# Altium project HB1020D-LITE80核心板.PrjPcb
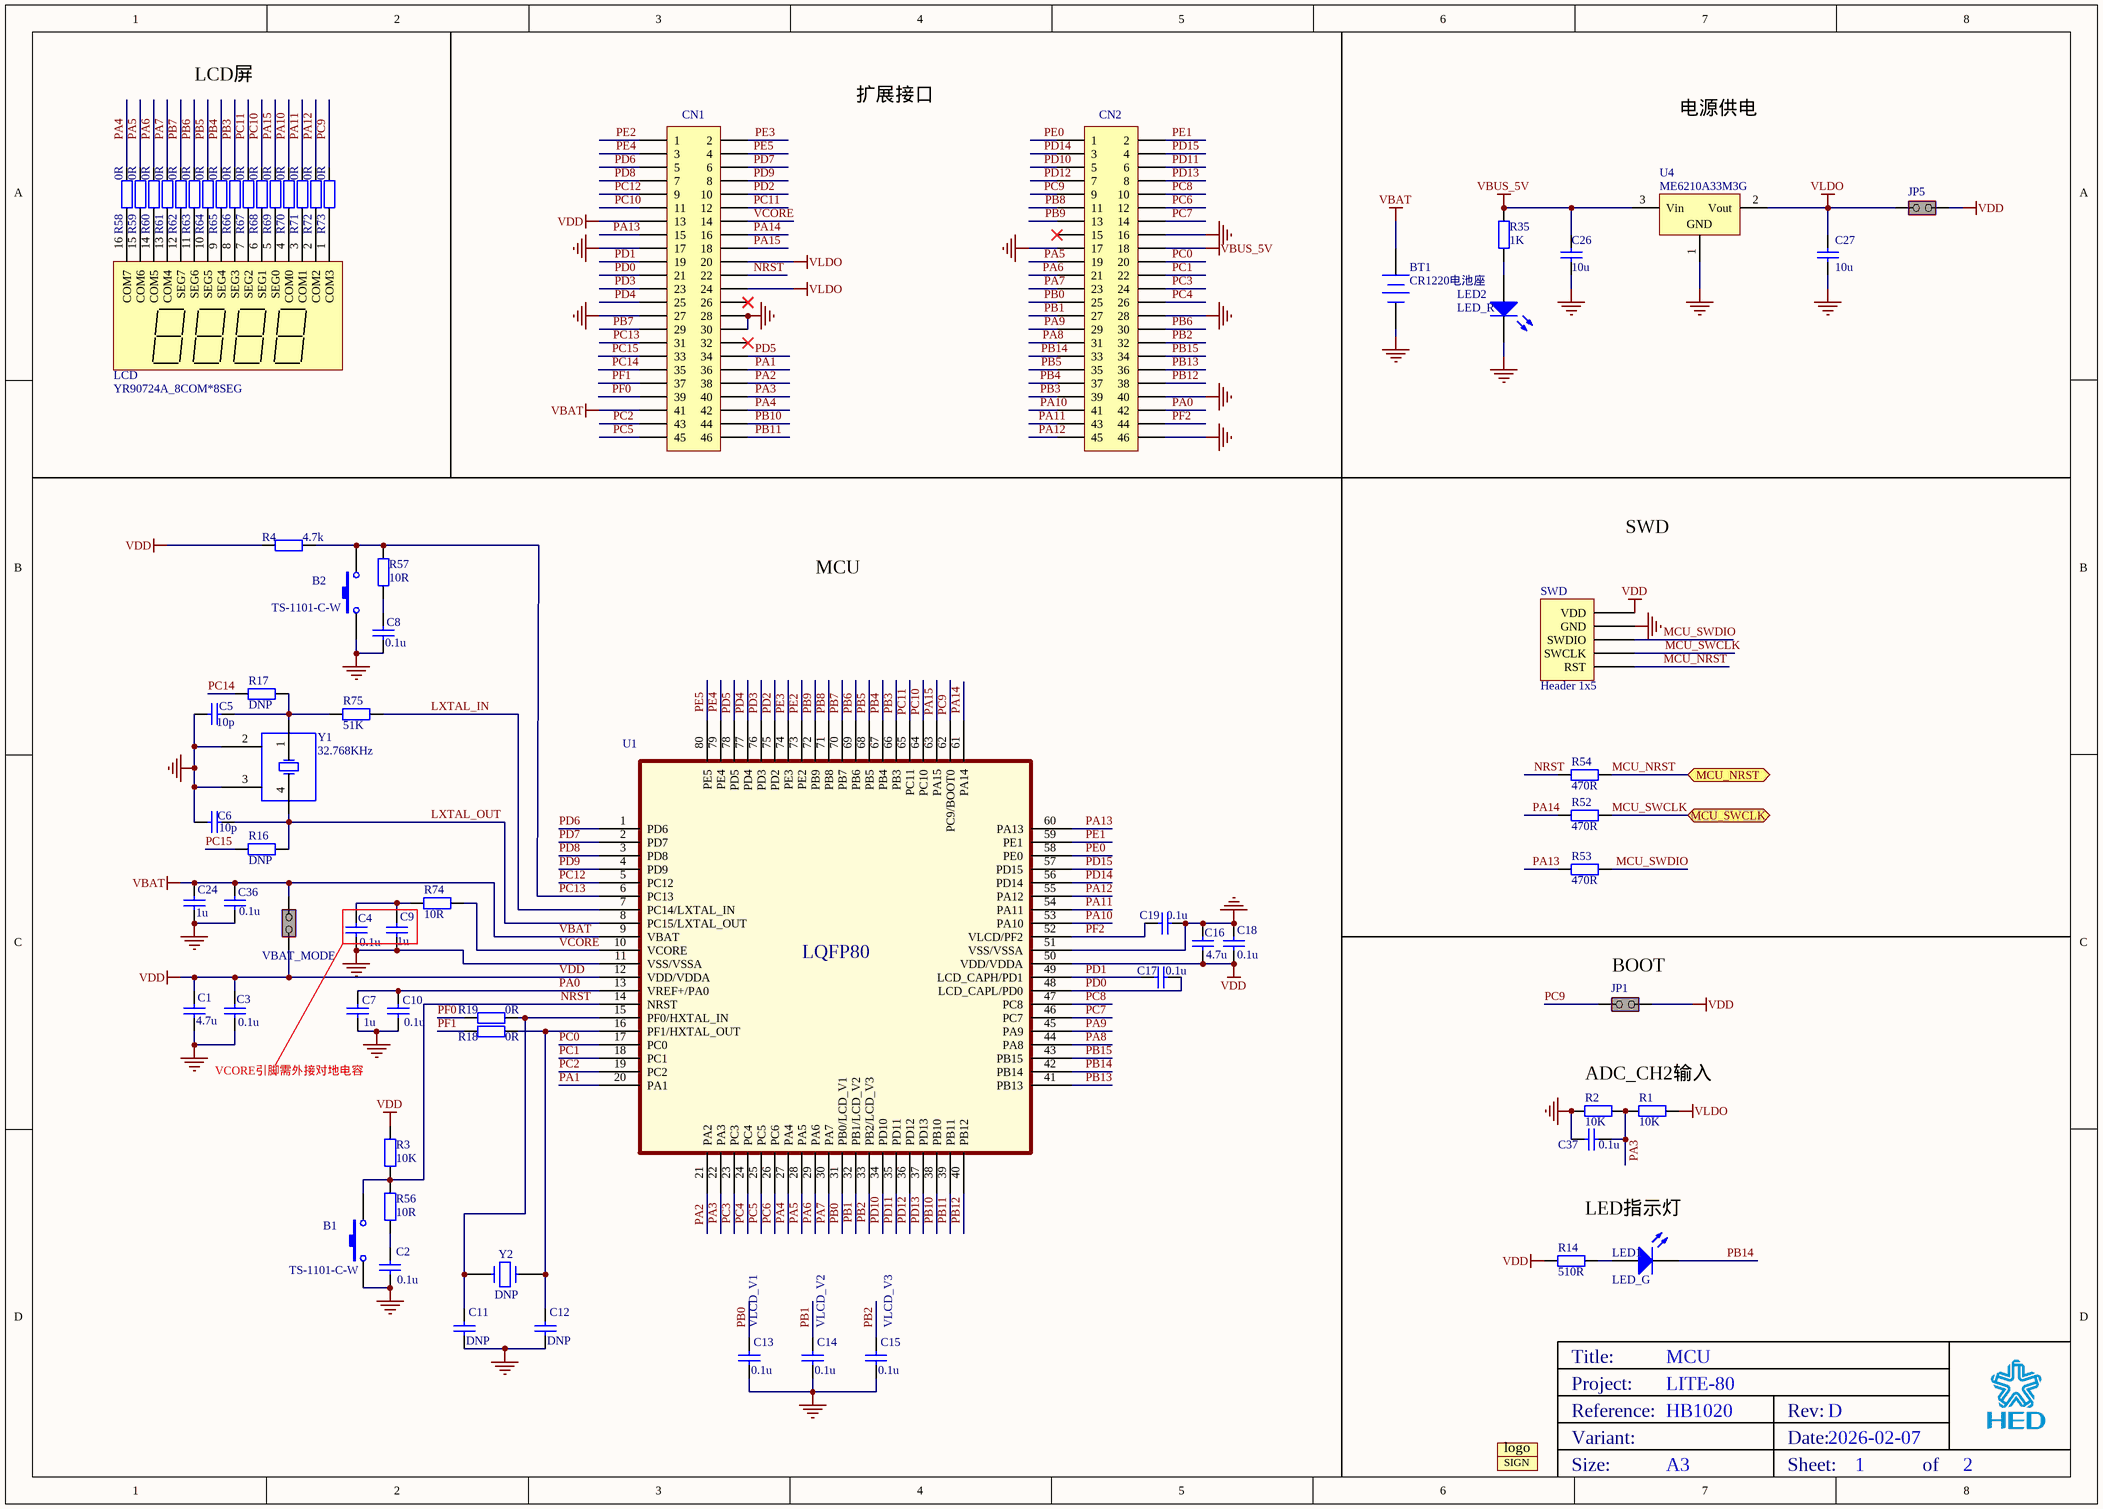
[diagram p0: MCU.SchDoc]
Board_Assembly_Revision: 01; Board_Name: LITE-80; Board_PCB_Revision: D; Board_Reference: HB1020
2 sheets, 115 parts. Net scope: global (net labels, ports and power ports of the same name join across sheets).
Board file: HB1020D.PcbDoc
Sheets:
  MCU.SchDoc
  LINK.SchDoc

## Sheet MCU.SchDoc: MCU
size A3; Date: 2026-02-07; SheetNumber: 1; SheetTotal: 2

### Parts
B1  TS-1101-C-W  [按键_TS-1101-C-W]
B2  TS-1101-C-W  [按键_TS-1101-C-W]
BT1  CR1220电池座  [CR1220]
C1  4.7u  [0603]
C2  0.1u  [0603]
C3  0.1u  [0603]
C4  0.1u  [0603]
C5  10p  [0603]
C6  10p  [0603]
C7  1u  [0603]
C8  0.1u  [0603]
C9  1u  [0603]
C10  0.1u  [0603]
C11  DNP  [0603]
C12  DNP  [0603]
C13  0.1u  [0603]
C14  0.1u  [0603]
C15  0.1u  [0603]
C16  4.7u  [0603]
C17  0.1u  [0603]
C18  0.1u  [0603]
C19  0.1u  [0603]
C24  1u  [0603]
C26  10u  [0603]
C27  10u  [0603]
C36  0.1u  [0603]
C37  0.1u  [0603]
CN1  Header 23x2  [HEADER_1X23_2.54]  (value not drawn)
CN2  Header 23x2  [HEADER_1X23_2.54]  (value not drawn)
JP1  Header 1x2  [HEADER_1X2_2.54]  (value not drawn)
JP5  Header 1x2  [HEADER_1X2_2.54]  (value not drawn)
LCD  YR90724A_8COM*8SEG  [LCD_YR_8COM*8SEG]
LED1  LED_G  [0603 - p]
LED2  LED_R  [0603-P]
logo1  logo  [LOGO]  (value not drawn)
logo2  SIGN  [SIGN]  (value not drawn)
R1  10K  [0603]
R2  10K  [0603]
R3  10K  [0603]
R4  4.7k  [0603]
R14  510R  [0603]
R16  DNP  [0603]
R17  DNP  [0603]
R18  0R  [0603]
R19  0R  [0603]
R35  1K  [0603]
R52  470R  [0603]
R53  470R  [0603]
R54  470R  [0603]
R56  10R  [0603]
R57  10R  [0603]
R58  0R  [0603]
R59  0R  [0603]
R60  0R  [0603]
R61  0R  [0603]
R62  0R  [0603]
R63  0R  [0603]
R64  0R  [0603]
R65  0R  [0603]
R66  0R  [0603]
R67  0R  [0603]
R68  0R  [0603]
R69  0R  [0603]
R70  0R  [0603]
R71  0R  [0603]
R72  0R  [0603]
R73  0R  [0603]
R74  10R  [0603]
R75  51K  [0603]
SWD  Header 1x5  [HDR1X5_2.54]
U1  (no value)  [LQFP_80N_12X12]
U4  ME6210A33M3G  [SOT-23-3]
VBAT_MODE  Header 1x2  [HEADER_1X2_2.54]  (value not drawn)
Y1  32.768KHz  [XTAL-MC146]
Y2  DNP  [XTAL_HC49/SMD]

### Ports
MCU_NRST, MCU_SWCLK

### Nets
GND: B1.1 B2.1 BT1.2(-) C1.1 C2.2 C3.1 C4.2 C5.1 C6.1 C7.1 C8.1 C9.2 C10.1 C11.2 C12.2 C13.2 C14.2 C15.2 C16.2 C18.2 C19.1 C24.1 C26.1 C27.1 C36.1 C37.2 CN1.17 CN1.27 CN1.28 CN1.30 CN2.16 CN2.17 CN2.28 CN2.40 CN2.46 LED2.2(K) R2.1 SWD.2(GND) U1.11(VSS/VSSA) U1.51(VSS/VSSA) U4.1(GND) Y1.2(OSC2) Y1.3(OSC4)
VBAT: BT1.1(+) C24.2 C36.2 CN1.41 U1.9(VBAT) VBAT_MODE.2(NO)
VBUS_5V: C26.2 CN2.18 R35.2 U4.3(Vin)
VDD: C1.2 C3.2 C16.1 C18.1 CN1.13 JP1.2(NO) JP5.1(COMMON) R3.1 R4.2 R14.2 SWD.1(VDD) U1.12(VDD/VDDA) U1.50(VDD/VDDA) VBAT_MODE.1(COMMON)
VLDO: C27.2 CN1.20 CN1.24 JP5.2(NO) R1.2 U4.2(Vout)
LXTAL_IN: R75.2 U1.7(PC14/LXTAL_IN)
LXTAL_OUT: C6.2 R16.2 U1.8(PC15/LXTAL_OUT) Y1.4(OSC3)
MCU_NRST: R54.1 SWD.5(RST) ; port MCU_NRST  [project net LINK_RESET]
MCU_SWCLK: R52.1 SWD.4(SWCLK) ; port MCU_SWCLK
MCU_SWDIO: R53.1 SWD.3(SWDIO)
NRST: B1.2 CN1.22 R3.2 R54.2 R56.1 U1.14(NRST)
PA0: C7.2 C10.2 CN2.42 U1.13(VREF+/PA0)
PA1: CN1.36 U1.20(PA1)
PA2: CN1.38 U1.21(PA2)
PA3: C37.1 CN1.40 R1.1 R2.2 U1.22(PA3)
PA4: CN1.42 R58.1 U1.27(PA4)
PA5: CN2.19 R59.1 U1.28(PA5)
PA6: CN2.21 R60.1 U1.29(PA6)
PA7: CN2.23 R61.1 U1.30(PA7)
PA8: CN2.31 U1.44(PA8)
PA9: CN2.29 U1.45(PA9)
PA10: CN2.41 R70.1 U1.53(PA10)
PA11: CN2.43 R71.1 U1.54(PA11)
PA12: CN2.45 R72.1 U1.55(PA12)
PA13: CN1.15 R53.2 U1.60(PA13)
PA14: CN1.16 R52.2 U1.61(PA14)
PA15: CN1.18 R69.1 U1.63(PA15)
PB0: C13.1 CN2.25 U1.31(PB0/LCD_V1)
PB1: C14.1 CN2.27 U1.32(PB1/LCD_V2)
PB2: C15.1 CN2.32 U1.33(PB2/LCD_V3)
PB3: CN2.39 R66.1 U1.66(PB3)
PB4: CN2.37 R65.1 U1.67(PB4)
PB5: CN2.35 R64.1 U1.68(PB5)
PB6: CN2.30 R63.1 U1.69(PB6)
PB7: CN1.29 R62.1 U1.70(PB7)
PB8: CN2.11 U1.71(PB8)
PB9: CN2.13 U1.72(PB9)
PB10: CN1.44 U1.38(PB10)
PB11: CN1.46 U1.39(PB11)
PB12: CN2.38 U1.40(PB12)
PB13: CN2.36 U1.41(PB13)
PB14: CN2.33 LED1.2(K) U1.42(PB14)
PB15: CN2.34 U1.43(PB15)
PC0: CN2.20 U1.17(PC0)
PC1: CN2.22 U1.18(PC1)
PC2: CN1.43 U1.19(PC2)
PC3: CN2.24 U1.23(PC3)
PC4: CN2.26 U1.24(PC4)
PC5: CN1.45 U1.25(PC5)
PC6: CN2.12 U1.26(PC6)
PC7: CN2.14 U1.46(PC7)
PC8: CN2.10 U1.47(PC8)
PC9: CN2.9 JP1.1(COMMON) R73.1 U1.62(PC9/BOOT0)
PC10: CN1.11 R68.1 U1.64(PC10)
PC11: CN1.12 R67.1 U1.65(PC11)
PC12: CN1.9 U1.5(PC12)
PC13: B2.2 CN1.31 R4.1 R57.1 U1.6(PC13)
PC14: CN1.35 R17.1
PC15: CN1.33 R16.1
PD0: C17.1 CN1.21 U1.48(LCD_CAPL/PD0)
PD1: C17.2 CN1.19 U1.49(LCD_CAPH/PD1)
PD2: CN1.10 U1.75(PD2)
PD3: CN1.23 U1.76(PD3)
PD4: CN1.25 U1.77(PD4)
PD5: CN1.34 U1.78(PD5)
PD6: CN1.5 U1.1(PD6)
PD7: CN1.6 U1.2(PD7)
PD8: CN1.7 U1.3(PD8)
PD9: CN1.8 U1.4(PD9)
PD10: CN2.5 U1.34(PD10)
PD11: CN2.6 U1.35(PD11)
PD12: CN2.7 U1.36(PD12)
PD13: CN2.8 U1.37(PD13)
PD14: CN2.3 U1.56(PD14)
PD15: CN2.4 U1.57(PD15)
PE0: CN2.1 U1.58(PE0)
PE1: CN2.2 U1.59(PE1)
PE2: CN1.1 U1.73(PE2)
PE3: CN1.2 U1.74(PE3)
PE4: CN1.3 U1.79(PE4)
PE5: CN1.4 U1.80(PE5)
PF0: CN1.39 R19.2
PF1: CN1.37 R18.2
PF2: C19.2 CN2.44 U1.52(VLCD/PF2)
VCORE: CN1.14 R74.2 U1.10(VCORE)
NetC2_1: C2.1 R56.2
NetC4_1: C4.1 C9.1 R74.1
NetC5_2: C5.2 R17.2 R75.1 Y1.1(OSC1)
NetC8_2: C8.2 R57.2
NetC11_1: C11.1 R19.1 U1.15(PF0/HXTAL_IN) Y2.1
NetC12_1: C12.1 R18.1 U1.16(PF1/HXTAL_OUT) Y2.2
NetLCD_1: LCD.1(COM3) R73.2
NetLCD_2: LCD.2(COM2) R72.2
NetLCD_3: LCD.3(COM1) R71.2
NetLCD_4: LCD.4(COM0) R70.2
NetLCD_5: LCD.5(SEG0) R69.2
NetLCD_6: LCD.6(SEG1) R68.2
NetLCD_7: LCD.7(SEG2) R67.2
NetLCD_8: LCD.8(SEG3) R66.2
NetLCD_9: LCD.9(SEG4) R65.2
NetLCD_10: LCD.10(SEG5) R64.2
NetLCD_11: LCD.11(SEG6) R63.2
NetLCD_12: LCD.12(SEG7) R62.2
NetLCD_13: LCD.13(COM4) R61.2
NetLCD_14: LCD.14(COM5) R60.2
NetLCD_15: LCD.15(COM6) R59.2
NetLCD_16: LCD.16(COM7) R58.2
NetLED1_1: LED1.1(A) R14.1
NetLED2_1: LED2.1(A) R35.1

Not connected (* = marked no-connect by the designer): CN1 26* 32*; CN2 15*

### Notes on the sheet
- LCD屏
- 扩展接口
- 电源供电
- MCU
- SWD
- (near JP1) BOOT
- VCORE引脚需外接对地电容
- ADC_CH2输入
- LED指示灯
- (near C13) VLCD_V1
- (near C14) VLCD_V2
- (near C15) VLCD_V3

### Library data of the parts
B1 B2 = SW-PB: 贴片按键
BT1 = Battery: 贴片CR1220电池座
C1 C13-C17 C19 C24 C36 C37 = MCD-00009: Capacitor, MLCC, 4.7uF, 16V, X5R, 10%, 0603, T=0.8mm; Manufacturer_Part_Number: CC0603KRX5R7BB475; Manufacturer: YAGEO; Provided_By: subcon; Initial_Board_Reference: mb1274
C2-C4 C7 C9 C10 C18 = MCD-00211: Capacitor, MLCC, 100nF, 16V, X7R, 10%, 0603, T=0,8mm; Manufacturer_Part_Number: CC0603KRX7R7BB104; Manufacturer: YAGEO; Provided_By: Subcon; Initial_Board_Reference: mb1319
C5 C6 = MCD-00666: Capacitor,5.6pF,0.1pF,16V,NPO,0603; Manufacturer_Part_Number: CC0603BRNPO7BN5R6; Manufacturer: YAGEO; Provided_By: Subcon; Initial_Board_Reference: MB1360
C8 = MCD-00211: 贴片电容; Manufacturer_Part_Number: CC0603KRX7R7BB104; Manufacturer: YAGEO; Provided_By: Subcon; Initial_Board_Reference: mb1319
C11 C12 = MCD-00009: 贴片电容33p; Manufacturer_Part_Number: CC0603KRX5R7BB475; Manufacturer: YAGEO; Provided_By: subcon; Initial_Board_Reference: mb1274
C26 C27 = MCD-00014: Capacitor, MLCC, 10uF, 25V, X5R, 10%, 0805, T=0,85mm; Manufacturer_Part_Number: CC0805KRX5R8BB106; Manufacturer: YAGEO; Provided_By: Subcon; Initial_Board_Reference: mb1274
CN1 CN2 = Header 23x2: Header, 19x2, 2,54mm, VR, TH, Height 5.84mm/10.16mm; Internal_Part_Number: MCD-00213; Manufacturer: SAMTEC; Part_Type: Connector; Manufacturer_Part_Number: TSW-119-09-x-D1; Value: Header 19x2; Provided_By: Subcon; Initial_Board_Reference: mb1319
JP1 JP5 VBAT_MODE = MCD-00683: Header, 2x1, 2,54mm, VR, TH, Height 5.84mm/2.54mm - Shunt Fitted by default; Part_Type: Connector; Manufacturer_Part_Number: TSW-102-07-x-S; Manufacturer: SAMTEC; Provided_By: Subcon; Initial_Board_Reference: MB1331
LCD = LCD8COM*8SEG: Common Anode Seven-Segment Display, Right Hand Decimal; Manufacturer: 苏州扬润电子
LED1 = LED1: 贴片LED 绿色
LED2 = LED1: 贴片LED 红色
R1-R3 R35 R58-R73 = Res2: 贴片电阻
R4 R14 R16-R19 R56 R57 R74 R75 = Res2: 贴片电阻; Value: 1K
R52-R54 = Res: 贴片电阻; Value: 51R
SWD = SWD: Header, 1x5, 2,54mm, VR, TH, Height 5.84mm/2.54mm
U1 = CIU32L071Mx-LQFP80: CIU32L071Mx
U4 = ME6210: 贴片LDO3.3V; Manufacturer: 微盟电子
Y1 = MC146: 贴片晶振
Y2 = XTAL_32K_NX3215SA: Crystal 32.768kHz, 6pF, -+20PPM, R=50K, SMD; Internal_Part_Number: MCD-00091; Part_Type: Crystal_Osc; Manufacturer_Part_Number: NX3215SA 32.768KHz EXS00A-MU00525; Manufacturer: NDK; ECCN_US: EAR99; ECCN_EU: NEC; Provided_By: STM; Initial_Board_Reference: mb1274

## Sheet LINK.SchDoc: LINK
size A4; Date: 2025-03-10; SheetNumber: 2; SheetTotal: 2
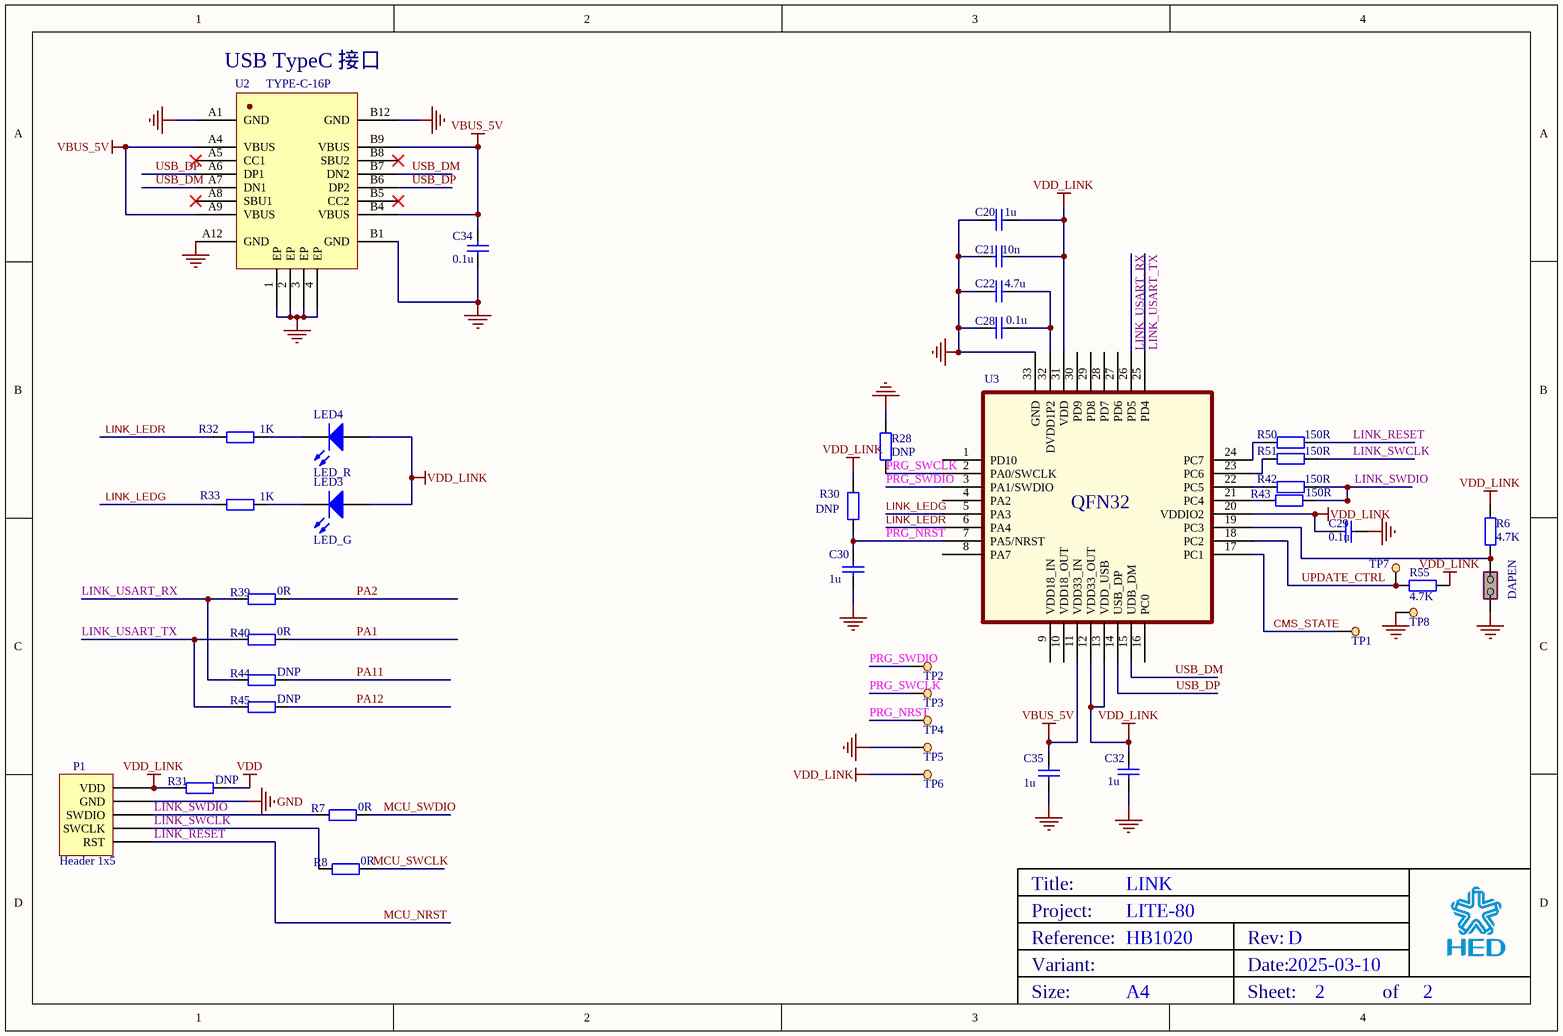
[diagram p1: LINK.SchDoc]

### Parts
C20  1u  [0603]
C21  10n  [0603]
C22  4.7u  [0603]
C28  0.1u  [0603]
C29  0.1u  [0603]
C30  value 1u  [0603]  (hidden comment: 0.1u)
C32  1u  [0603]
C34  0.1u  [0603]
C35  1u  [0603]
DAPEN  Header 1x2  [HEADER_1X2_2.54]  (value not drawn)
LED3  LED_G  [0603-P]
LED4  LED_R  [0603-P]
P1  Header 1x5  [HDR1X5_2.54]
R6  4.7K  [0603]
R7  0R  [0603]
R8  0R  [0603]
R28  DNP  [0603]
R30  DNP  [0603]
R31  DNP  [0603]
R32  1K  [0603]
R33  1K  [0603]
R39  0R  [0603]
R40  0R  [0603]
R42  150R  [0603]
R43  150R  [0603]
R44  DNP  [0603]
R45  DNP  [0603]
R50  150R  [0603]
R51  150R  [0603]
R55  4.7K  [0603]
TP1  TEST_POINT  [TEST_POINT]  (value not drawn)
TP2  TEST_POINT  [TEST_POINT]  (value not drawn)
TP3  TEST_POINT  [TEST_POINT]  (value not drawn)
TP4  TEST_POINT  [TEST_POINT]  (value not drawn)
TP5  TEST_POINT  [TEST_POINT]  (value not drawn)
TP6  TEST_POINT  [TEST_POINT]  (value not drawn)
TP7  TEST_POINT  [TEST_POINT]  (value not drawn)
TP8  TEST_POINT  [TEST_POINT]  (value not drawn)
U2  TYPE-C-16P  [HED-KH-TYPE-C-16P]
U3  CIU98_H  [HED-QFN-32_5x5x05P]  (value not drawn)

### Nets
GND: C20.1 C21.1 C22.1 C28.1 C29.1 C30.2 C32.2 C34.1 C35.2 DAPEN.2(NO) P1.2(GND) R28.1 TP5.1 TP8.1 U2.1(EP) U2.2(EP) U2.3(EP) U2.4(EP) U2.A1(GND) U2.A12(GND) U2.B1(GND) U2.B12(GND) U3.33(GND)
VBUS_5V: C34.2 C35.1 U2.A4(VBUS) U2.A9(VBUS) U2.B4(VBUS) U2.B9(VBUS) U3.11(VDD33_IN)
VDD: R31.2
VDD_LINK: C20.2 C21.2 C29.2 C32.1 LED3.1(A) LED4.1(A) P1.1(VDD) R6.2 R30.1 R31.1 R55.1 TP6.1 U3.12(VDD33_OUT) U3.13(VDD_USB) U3.20(VDDIO2) U3.31(VDD)
CMS_STATE: TP1.1 U3.17(PC1)
LINK_LEDG: R33.1 U3.5(PA3)
LINK_LEDR: R32.1 U3.6(PA4)
LINK_RESET: P1.5(RST) R50.2  [also labelled MCU_NRST]
LINK_SWCLK: P1.4(SWCLK) R8.1 R51.2
LINK_SWDIO: P1.3(SWDIO) R7.1 R42.2 R43.2
LINK_USART_RX: R39.1 R44.1 U3.26(PD5)
LINK_USART_TX: R40.1 R45.1 U3.25(PD4)
MCU_SWCLK: R8.2
MCU_SWDIO: R7.2
PA1: R40.2
PA2: R39.2
PA11: R44.2
PA12: R45.2
PRG_NRST: C30.1 R30.2 TP4.1 U3.7(PA5/NRST)
PRG_SWCLK: R28.2 TP3.1 U3.2(PA0/SWCLK)
PRG_SWDIO: TP2.1 U3.3(PA1/SWDIO)
UPDATE_CTRL: R55.2 TP7.1 U3.18(PC2)
USB_DM: U2.A7(DN1) U2.B7(DN2) U3.15(UDB_DM)
USB_DP: U2.A6(DP1) U2.B6(DP2) U3.14(USB_DP)
NetC22_2: C22.2 C28.2 U3.32(DVDD1P2)
NetDAPEN_1: DAPEN.1(COMMON) R6.1 U3.19(PC3)
NetLED3_2: LED3.2(K) R33.2
NetLED4_2: LED4.2(K) R32.2
NetR42_1: R42.1 U3.22(PC5)
NetR43_1: R43.1 U3.21(PC4)
NetR50_1: R50.1 U3.24(PC7)
NetR51_1: R51.1 U3.23(PC6)

Not connected (* = marked no-connect by the designer): U2 A5(CC1)* A8(SBU1)* B5(CC2)* B8(SBU2)*; U3 1(PD10) 4(PA2) 8(PA7) 9(VDD18_IN) 10(VDD18_OUT) 16(PC0) 27(PD6) 28(PD7) 29(PD8) 30(PD9)

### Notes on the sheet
- (near U2) USB TypeC 接口

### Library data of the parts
C20-C22 C28-C30 C32 C35 = MCD-00211: as C2 on sheet MCU
C34 = 0603 100nF 10% 50V: 贴片电容
DAPEN = MCD-00683: Header, 2x1, 2,54mm, VR, TH, Height 5.84mm/2.54mm; Part_Type: Connector; Manufacturer_Part_Number: TSW-102-07-x-S; Manufacturer: SAMTEC; Provided_By: Subcon; Initial_Board_Reference: MB1331
LED3 = LED1: 贴片LED 绿色
LED4 = LED1: 贴片LED 红色
P1 = SWD: as SWD on sheet MCU
R6 R55 = Res: 贴片电阻
R7 R8 R32 R33 R39 R40 R44 R45 = Res2: 贴片电阻
R28 R42 R43 R50 R51 = Res: 贴片电阻; Value: 1K
R30 R31 = Res2: 贴片电阻; Value: 1K
U2 = KH-TYPE-C-16P: TYPE-C USB接口
U3 = CIU98-H: 贴片芯片

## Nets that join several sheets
GND: MCU (43 pins), LINK (23 pins)
VBUS_5V: MCU (C26.2 CN2.18 R35.2 U4.3), LINK (7 pins)
VDD: MCU (14 pins), LINK (R31.2)
LINK_RESET: MCU (R54.1 SWD.5), LINK (P1.5 R50.2)
MCU_SWCLK: MCU (R52.1 SWD.4), LINK (R8.2)
MCU_SWDIO: MCU (R53.1 SWD.3), LINK (R7.2)
PA1: MCU (CN1.36 U1.20), LINK (R40.2)
PA2: MCU (CN1.38 U1.21), LINK (R39.2)
PA11: MCU (CN2.43 R71.1 U1.54), LINK (R44.2)
PA12: MCU (CN2.45 R72.1 U1.55), LINK (R45.2)

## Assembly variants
Default: all parts fitted
HB1020B01_BOM-L071: not fitted C11 C12 logo1 logo2 R16 R17 R28 R30 R31 R44 R45 TP1 TP2 TP3 TP4 TP5 TP6 TP7 TP8 Y2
